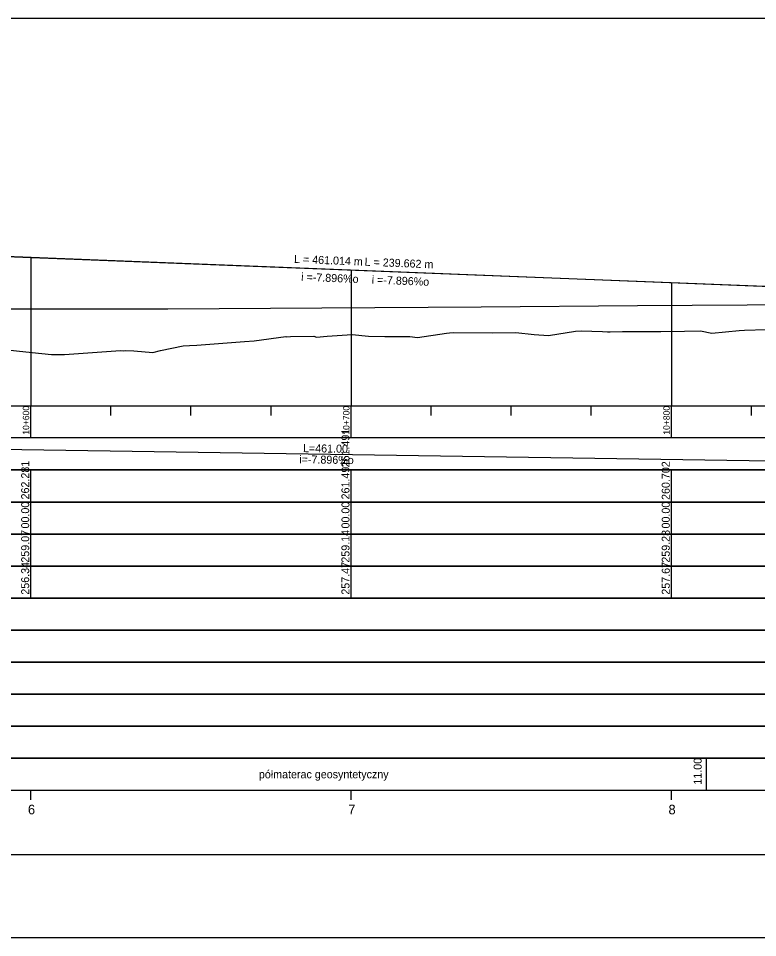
# Model space of a CAD drawing. Extents: x 6445630 to 6518227, y 5499240 to 5511716.
# Drawn here: x 6455227.3 to 6455458.1, y 5506751.3 to 5507038.3 of the extents above; entities that cross this region are included whole.
import ezdxf

# ---------------------------------------------------------------- set-up
doc = ezdxf.new("R2010")
doc.units = 0
for name, color, linetype in [('TOR_PROF-opisy pomocnicze', 7, 'Continuous'), ('TOR_PROF-tabelka-geometria T1', 7, 'Continuous'), ('TOR_PROF-tabelka-kilometracja', 7, 'Continuous'), ('TOR_PROF-tabelka-odleglosci T1', 7, 'Continuous'), ('TOR_PROF-tabelka-pochylenia proj T1', 7, 'Continuous'), ('TOR_PROF-tabelka-rodzaj rowu T1', 7, 'Continuous'), ('TOR_PROF-tabelka-rowyT1', 7, 'Continuous'), ('TOR_PROF-tabelka-rurociagi T1', 7, 'Continuous'), ('TOR_PROF-tabelka-rzedne istn T1', 7, 'Continuous'), ('TOR_PROF-tabelka-rzedne proj T1', 7, 'Continuous'), ('TOR_PROF-tabelka-teren istniejacy T1', 7, 'Continuous'), ('TOR_PROF-tabelka-warstwa ochronna T1', 7, 'Continuous'), ('TOR_PROF-tor istniejacy T2', 7, 'Continuous'), ('TOR_PROF-tor projektowany', 7, 'Continuous'), ('TOR_PROF-uklad odniesienia', 7, 'Continuous'), ('TOR_PROF-warstwa ochronna', 7, 'Continuous'), ('TOR_RAMKI-dodatkowe3', 7, 'Continuous'), ('TOR_RAMKI-MASKA WYCIECIA', 7, 'Continuous')]:
    doc.layers.add(name, color=color, linetype=linetype)

msp = doc.modelspace()

# ---------------------------------------------------------------- linework, layer by layer
at = {"layer": 'TOR_PROF-tabelka-geometria T1'}
for points in [[(6452423.2, 5506777.3), (6452515.66, 5506777.3), (6452515.66, 5506777.3), (6452555.66, 5506779.97), (6452555.66, 5506779.97), (6452695.25, 5506779.97), (6452695.25, 5506779.97), (6452735.25, 5506777.3), (6452735.25, 5506777.3), (6458247.17, 5506777.3)], [(6452331.21, 5506777.3), (6459531.21, 5506777.3)]]:
    msp.add_lwpolyline(points, dxfattribs=at)
at = {"layer": 'TOR_PROF-tabelka-kilometracja'}
for points in [[(6455231.21, 5506794.3), (6455231.21, 5506797.3)], [(6455331.21, 5506794.3), (6455331.21, 5506797.3)], [(6455431.21, 5506794.3), (6455431.21, 5506797.3)]]:
    msp.add_lwpolyline(points, dxfattribs=at)
at = {"layer": 'TOR_PROF-tabelka-odleglosci T1'}
msp.add_lwpolyline([(6452331.21, 5506877.3), (6459531.21, 5506877.3), (6459531.21, 5506887.3), (6452331.21, 5506887.3)], close=True, dxfattribs=at)
for points in [[(6455231.21, 5506877.3), (6455231.21, 5506887.3)], [(6455331.21, 5506877.3), (6455331.21, 5506887.3)], [(6455431.21, 5506877.3), (6455431.21, 5506887.3)]]:
    msp.add_lwpolyline(points, dxfattribs=at)
at = {"layer": 'TOR_PROF-tabelka-pochylenia proj T1'}
msp.add_lwpolyline([(6452331.21, 5506897.3), (6459531.21, 5506897.3), (6459531.21, 5506907.3), (6452331.21, 5506907.3)], close=True, dxfattribs=at)
msp.add_lwpolyline([(6455090.74, 5506905.8), (6455551.74, 5506898.8)], dxfattribs=at)
at = {"layer": 'TOR_PROF-tabelka-rodzaj rowu T1'}
for points in [[(6452331.21, 5506837.3), (6459531.21, 5506837.3), (6459531.21, 5506847.3), (6452331.21, 5506847.3)], [(6452331.21, 5506817.3), (6459531.21, 5506817.3), (6459531.21, 5506827.3), (6452331.21, 5506827.3)]]:
    msp.add_lwpolyline(points, close=True, dxfattribs=at)
at = {"layer": 'TOR_PROF-tabelka-rowyT1'}
msp.add_lwpolyline([(6452331.21, 5506847.3), (6459531.21, 5506847.3), (6459531.21, 5506857.3), (6452331.21, 5506857.3)], close=True, dxfattribs=at)
at = {"layer": 'TOR_PROF-tabelka-rurociagi T1'}
msp.add_lwpolyline([(6452331.21, 5506827.3), (6459531.21, 5506827.3), (6459531.21, 5506837.3), (6452331.21, 5506837.3)], close=True, dxfattribs=at)
at = {"layer": 'TOR_PROF-tabelka-rzedne istn T1'}
msp.add_lwpolyline([(6452331.21, 5506867.3), (6459531.21, 5506867.3), (6459531.21, 5506877.3), (6452331.21, 5506877.3)], close=True, dxfattribs=at)
for points in [[(6455231.21, 5506867.3), (6455231.21, 5506877.3)], [(6455331.21, 5506867.3), (6455331.21, 5506877.3)], [(6455431.21, 5506867.3), (6455431.21, 5506877.3)], [(6455231.21, 5506857.3), (6455231.21, 5506867.3)], [(6455231.21, 5506857.3), (6455231.21, 5506867.3)], [(6455231.21, 5506857.3), (6455231.21, 5506867.3)], [(6455331.21, 5506857.3), (6455331.21, 5506867.3)], [(6455331.21, 5506857.3), (6455331.21, 5506867.3)], [(6455331.21, 5506857.3), (6455331.21, 5506867.3)], [(6455431.21, 5506857.3), (6455431.21, 5506867.3)], [(6455431.21, 5506857.3), (6455431.21, 5506867.3)], [(6455431.21, 5506857.3), (6455431.21, 5506867.3)]]:
    msp.add_lwpolyline(points, dxfattribs=at)
at = {"layer": 'TOR_PROF-tabelka-rzedne proj T1'}
msp.add_lwpolyline([(6452331.21, 5506887.3), (6459531.21, 5506887.3), (6459531.21, 5506897.3), (6452331.21, 5506897.3)], close=True, dxfattribs=at)
for points in [[(6455231.21, 5506887.3), (6455231.21, 5506897.3)], [(6455331.21, 5506887.3), (6455331.21, 5506897.3)], [(6455431.21, 5506887.3), (6455431.21, 5506897.3)]]:
    msp.add_lwpolyline(points, dxfattribs=at)
at = {"layer": 'TOR_PROF-tabelka-teren istniejacy T1'}
msp.add_lwpolyline([(6452331.21, 5506857.3), (6459531.21, 5506857.3), (6459531.21, 5506867.3), (6452331.21, 5506867.3)], close=True, dxfattribs=at)
msp.add_lwpolyline([(6452331.21, 5506857.3), (6459531.21, 5506857.3), (6459531.21, 5506867.3), (6452331.21, 5506867.3)], close=True, dxfattribs=at)
msp.add_lwpolyline([(6452331.21, 5506857.3), (6459531.21, 5506857.3), (6459531.21, 5506867.3), (6452331.21, 5506867.3)], close=True, dxfattribs=at)
at = {"layer": 'TOR_PROF-tabelka-warstwa ochronna T1'}
msp.add_lwpolyline([(6452331.21, 5506807.3), (6459531.21, 5506807.3), (6459531.21, 5506817.3), (6452331.21, 5506817.3)], close=True, dxfattribs=at)
at = {"layer": 'TOR_PROF-tor istniejacy T2'}
msp.add_lwpolyline([(6455222.98, 5506947.65), (6455274.03, 5506947.65), (6455322.06, 5506947.95), (6455371.83, 5506948.25), (6455420.66, 5506948.65), (6455471.92, 5506949), (6455520.99, 5506949.25), (6455570.38, 5506949.3), (6455621.58, 5506949.6), (6455671.91, 5506949.9), (6455721.22, 5506950.2), (6455771.37, 5506950.4)], dxfattribs=at)
at = {"layer": 'TOR_PROF-tor projektowany'}
for p, q in [((6455090.74, 5506969.25), (6455551.74, 5506951.05)), ((6455223.46, 5506964.01), (6455463.11, 5506954.55))]:
    msp.add_line(p, q, dxfattribs=at)
for points in [[(6455231.21, 5506963.71), (6455231.21, 5506922.3), (6455231.21, 5506917.3), (6455231.21, 5506917.3)], [(6455231.21, 5506963.71), (6455231.21, 5506922.3), (6455231.21, 5506917.3), (6455231.21, 5506917.3)], [(6455331.21, 5506959.76), (6455331.21, 5506922.3), (6455331.21, 5506917.3), (6455331.21, 5506917.3)], [(6455331.21, 5506959.76), (6455331.21, 5506922.3), (6455331.21, 5506917.3), (6455331.21, 5506917.3)], [(6455331.21, 5506959.76), (6455331.21, 5506922.3), (6455331.21, 5506917.3), (6455331.21, 5506917.3)], [(6455431.21, 5506955.81), (6455431.21, 5506922.3), (6455431.21, 5506917.3), (6455431.21, 5506917.3)], [(6455431.21, 5506955.81), (6455431.21, 5506922.3), (6455431.21, 5506917.3), (6455431.21, 5506917.3)]]:
    msp.add_lwpolyline(points, dxfattribs=at)
at = {"layer": 'TOR_PROF-uklad odniesienia'}
for p, q in [((6452331.21, 5506917.3), (6459531.21, 5506917.3)), ((6455231.21, 5506907.3), (6455231.21, 5506917.3)), ((6455256.21, 5506914.3), (6455256.21, 5506917.3)), ((6455281.21, 5506914.3), (6455281.21, 5506917.3)), ((6455306.21, 5506914.3), (6455306.21, 5506917.3)), ((6455331.21, 5506907.3), (6455331.21, 5506917.3)), ((6455356.21, 5506914.3), (6455356.21, 5506917.3)), ((6455381.21, 5506914.3), (6455381.21, 5506917.3)), ((6455406.21, 5506914.3), (6455406.21, 5506917.3)), ((6455431.21, 5506907.3), (6455431.21, 5506917.3)), ((6455456.21, 5506914.3), (6455456.21, 5506917.3))]:
    msp.add_line(p, q, dxfattribs=at)
at = {"layer": 'TOR_PROF-warstwa ochronna'}
msp.add_lwpolyline([(6452331.21, 5506797.3), (6459531.21, 5506797.3), (6459531.21, 5506807.3), (6452331.21, 5506807.3)], close=True, dxfattribs=at)
msp.add_lwpolyline([(6455442.21, 5506797.3), (6455442.21, 5506807.3)], dxfattribs=at)
at = {"layer": 'TOR_RAMKI-dodatkowe3'}
for p, q in [((6455300.92, 5506937.64), (6455310.82, 5506938.93)), ((6455310.82, 5506938.93), (6455311.13, 5506938.91)), ((6455311.13, 5506938.91), (6455312.32, 5506938.96)), ((6455312.32, 5506938.96), (6455319.6, 5506939.04)), ((6455319.6, 5506939.04), (6455320.38, 5506938.8)), ((6455320.38, 5506938.8), (6455323.75, 5506939.12)), ((6455323.75, 5506939.12), (6455331.57, 5506939.65)), ((6455331.57, 5506939.65), (6455336.67, 5506939.08)), ((6455336.67, 5506939.08), (6455341.78, 5506938.97)), ((6455341.78, 5506938.97), (6455349.6, 5506938.93)), ((6455349.6, 5506938.93), (6455352, 5506938.7)), ((6455352, 5506938.7), (6455361.02, 5506940.02)), ((6455361.02, 5506940.02), (6455361.93, 5506940.15)), ((6455361.93, 5506940.15), (6455363.07, 5506940.19)), ((6455363.07, 5506940.19), (6455375.46, 5506940.12)), ((6455375.46, 5506940.12), (6455382.64, 5506940.25)), ((6455382.64, 5506940.25), (6455388.38, 5506939.56)), ((6455388.38, 5506939.56), (6455392.86, 5506939.32)), ((6455392.86, 5506939.32), (6455401.31, 5506940.69)), ((6455401.31, 5506940.69), (6455403.08, 5506940.74)), ((6455403.08, 5506940.74), (6455409.72, 5506940.59)), ((6455409.72, 5506940.59), (6455411.26, 5506940.43)), ((6455411.26, 5506940.43), (6455412.14, 5506940.45)), ((6455412.14, 5506940.45), (6455416, 5506940.54)), ((6455416, 5506940.54), (6455427.95, 5506940.59)), ((6455427.95, 5506940.59), (6455435.3, 5506940.69)), ((6455435.3, 5506940.69), (6455440.27, 5506940.74)), ((6455440.27, 5506940.74), (6455443.88, 5506939.97)), ((6455443.88, 5506939.97), (6455452.41, 5506940.85)), ((6455452.41, 5506940.85), (6455454.07, 5506940.97)), ((6455454.07, 5506940.97), (6455460.78, 5506941.16)), ((6455271.71, 5506934.63), (6455278.8, 5506936.09)), ((6455278.8, 5506936.09), (6455280.73, 5506936.17)), ((6455280.73, 5506936.17), (6455283.02, 5506936.26)), ((6455283.02, 5506936.26), (6455297.89, 5506937.44)), ((6455297.89, 5506937.44), (6455300.92, 5506937.64)), ((6455221.83, 5506935.02), (6455231.64, 5506933.96)), ((6455231.64, 5506933.96), (6455237.64, 5506933.39)), ((6455237.64, 5506933.39), (6455241.68, 5506933.33)), ((6455241.68, 5506933.33), (6455259.19, 5506934.56)), ((6455259.19, 5506934.56), (6455260.07, 5506934.53)), ((6455260.07, 5506934.53), (6455260.64, 5506934.58)), ((6455260.64, 5506934.58), (6455263.4, 5506934.54)), ((6455263.4, 5506934.54), (6455269.29, 5506933.98)), ((6455269.29, 5506933.98), (6455271.71, 5506934.63))]:
    msp.add_line(p, q, dxfattribs=at)
at = {"layer": 'TOR_RAMKI-MASKA WYCIECIA'}
msp.add_lwpolyline([(6453880.05, 5506751.3), (6455570.05, 5506751.3), (6455570.05, 5507038.3), (6453880.05, 5507038.3)], close=True, dxfattribs=at)

# ---------------------------------------------------------------- texts
at = {"layer": 'TOR_PROF-opisy pomocnicze'}
for s, p in [('L = 461.014 m', (6455313.36, 5506961.96)), ('L = 239.662 m', (6455335.4, 5506961.09)), ('  i =-7.896%o', (6455313.73, 5506956.45)), ('  i =-7.896%o', (6455335.77, 5506955.58))]:
    msp.add_text(s, height=2.5, rotation=357.7392, dxfattribs=at).set_placement(p)
at = {"layer": 'TOR_PROF-tabelka-kilometracja'}
for s, p in [('6', (6455230.32, 5506789.8)), ('7', (6455330.32, 5506789.8)), ('8', (6455430.32, 5506789.8))]:
    msp.add_text(s, height=3, dxfattribs=at).set_placement(p)
at = {"layer": 'TOR_PROF-tabelka-odleglosci T1'}
for p in [(6455230.71, 5506879.04), (6455330.71, 5506879.04), (6455430.71, 5506879.04)]:
    msp.add_text('00.00', height=2.5, rotation=90, dxfattribs=at).set_placement(p)
at = {"layer": 'TOR_PROF-tabelka-pochylenia proj T1'}
for s, rotation, p in [('261.491', 90, (6455330.71, 5506898.11)), ('L=461.00', 359.1301, (6455316.18, 5506902.88)), ('i=-7.896%o', 359.1301, (6455315.02, 5506899.4))]:
    msp.add_text(s, height=2.5, rotation=rotation, dxfattribs=at).set_placement(p)
at = {"layer": 'TOR_PROF-tabelka-rzedne istn T1'}
for s, p in [('259.07', (6455230.71, 5506868.37)), ('259.14', (6455330.71, 5506868.37)), ('259.28', (6455430.71, 5506868.36)), ('256.34', (6455230.71, 5506858.37)), ('257.47', (6455330.71, 5506858.37)), ('257.67', (6455430.71, 5506858.37))]:
    msp.add_text(s, height=2.5, rotation=90, dxfattribs=at).set_placement(p)
at = {"layer": 'TOR_PROF-tabelka-rzedne proj T1'}
for s, p in [('262.281', (6455230.71, 5506888.11)), ('261.491', (6455330.71, 5506888.11)), ('260.702', (6455430.71, 5506887.95))]:
    msp.add_text(s, height=2.5, rotation=90, dxfattribs=at).set_placement(p)
at = {"layer": 'TOR_PROF-uklad odniesienia'}
for s, p in [('10+600', (6455230.71, 5506908.32)), ('10+700', (6455330.71, 5506908.32)), ('10+800', (6455430.71, 5506908.32))]:
    msp.add_text(s, height=2, rotation=90, dxfattribs=at).set_placement(p)
at = {"layer": 'TOR_PROF-warstwa ochronna'}
msp.add_text('11.00', height=2.5, rotation=90, dxfattribs=at).set_placement((6455440.67, 5506799.05))
msp.add_text('półmaterac geosyntetyczny', height=2.5, dxfattribs=at).set_placement((6455302.42, 5506801.05))

doc.saveas('drawing.dxf')
